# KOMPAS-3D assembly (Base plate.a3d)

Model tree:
1. X Axis
2. Y Axis
3. Z Axis
4. Origin
5. Linear Pattern:1  (labels: Instance ( 2, 1 );; Instance ( 3, 1 );; Instance ( 4, 1 );; Instance ( 5, 1 );)
     Included Angle = 90; N 2 = 1; Spacing 2 = 10; Orientation = 1; Distance = 60; Orientation = 1

Expressions: W_BP+(2*Delta); L_BP-100-(Delta*2)
Referenced files in D:\Documents and Settings\kashirsky\Рабочий стол\My sample\: skrzynia1.a3d|L, skrzynia1.a3d|NR_Base, skrzynia1.a3d|W, Base plate.m3d, rail1.m3d, Base plate.a3d, Base plate.spw, skrzynia1.a3d, skrzynia1.spw, Box.cdw
Referenced files in C:\Work\01 К О М П А С\Модели примеры\2009_04_For_Poland_AXAPACK\My sample\: skrzynia1.a3d
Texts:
  Plate 00
  Wood (15% moisture content)
  Three Point Plane
  Plane at Angle
  Line and Point Plane
  Axis through Two Vertices
  Axis of Feature
  Axis of Conical Surface
  Axis through Edge
  Trim by Surface
  Trim by Sketch
  Intersection Axis of Two Planes
  Two Line Plane
  Line and Face Plane
  Pattern by Sample
  Point in CM
  Feature with No History
  Linear Dimension from Line to Point
  Surface Finish Symbol
  Geometric Tolerance Symbol
  Leader #1
  Leader #2
  Leader #3
  Shape Deviations and Datum
  Node point number
  Mark of coordination axis
  Node point designation
  Mark/Reference designation with leader
  Mark/reference designation on line
  Mark/Reference designation without leader
  Plate 01
  Rail 01
  Instance ( 2, 1 );
  Instance ( 3, 1 );
  Instance ( 4, 1 );
  Instance ( 5, 1 );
